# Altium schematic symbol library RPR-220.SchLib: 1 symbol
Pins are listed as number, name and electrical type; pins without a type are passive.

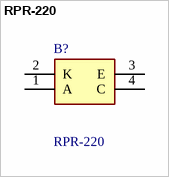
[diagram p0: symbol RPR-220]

## RPR-220
designator B?
PHOTOINTERRUPTER REFL 6MM 800NM Reflective Optical Sensor 0.236" (6mm) Radial - 4 Leads; Manufacturer_Name: ROHM Semiconductor; Geometry.Height: 6.7mm
footprint RPR220
pins: 1 A, 2 K, 3 E, 4 C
